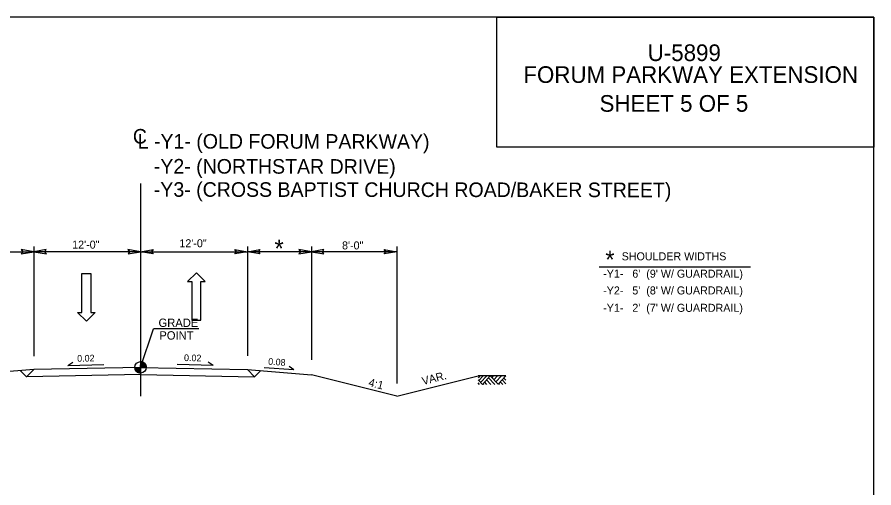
# Model space of a CAD drawing. Extents: x 1904401 to 1905163, y 193929 to 194736.
# Drawn here: x 1904562 to 1904658.3, y 194298.3 to 194351.2 of the extents above; entities that cross this region are included whole.
import ezdxf

# ---------------------------------------------------------------- set-up
doc = ezdxf.new("R2010")
doc.units = 0
for name, color, linetype in [('Old_Level_2', 7, 'Continuous'), ('Prop Dimension Text', 7, 'Continuous'), ('Prop Lane Arrow CELL', 7, 'Continuous'), ('Typical Arrow Superelevation CELL', 7, 'Continuous'), ('Typical Grade Point Symbol CELL', 7, 'Continuous'), ('Typical Hinge Slope Interstate CELL', 7, 'Continuous'), ('Typical Terminator CELL', 7, 'Continuous'), ('Typical Text Centerline CELL', 7, 'Continuous'), ('Typical Text Grade Point CELL', 7, 'Continuous')]:
    doc.layers.add(name, color=color, linetype=linetype)

msp = doc.modelspace()

# ---------------------------------------------------------------- linework, layer by layer
at = {"layer": 'Old_Level_2'}
msp.add_lwpolyline([(1904502.509, 194232.165), (1904658.329, 194232.165), (1904658.329, 194351.235), (1904502.509, 194351.235)], close=True, dxfattribs=at)
at = {"layer": 'Prop Dimension Text'}
msp.add_lwpolyline([(1904615.948, 194351.235), (1904658.329, 194351.235), (1904658.329, 194336.604), (1904615.948, 194336.604)], close=True, dxfattribs=at)
at = {"layer": 'Prop Lane Arrow CELL'}
for p, q in [((1904563.917, 194325.455), (1904563.917, 194313.121)), ((1904587.917, 194325.455), (1904587.917, 194313.144)), ((1904595.117, 194325.455), (1904595.117, 194312.685)), ((1904604.717, 194325.455), (1904604.717, 194310.019)), ((1904556.717, 194324.855), (1904563.917, 194324.855)), ((1904575.917, 194324.855), (1904563.917, 194324.855)), ((1904575.917, 194324.855), (1904587.917, 194324.855)), ((1904604.717, 194324.855), (1904587.917, 194324.855)), ((1904582.197, 194322.484), (1904581.201, 194321.503)), ((1904583.162, 194321.503), (1904582.197, 194322.484)), ((1904627.471, 194323.163), (1904644.479, 194323.163)), ((1904569.311, 194322.389), (1904570.338, 194322.389)), ((1904569.311, 194318.032), (1904569.311, 194322.389)), ((1904570.338, 194322.389), (1904570.338, 194318.032)), ((1904581.201, 194321.503), (1904581.668, 194321.503)), ((1904581.668, 194321.503), (1904581.668, 194317.146)), ((1904582.695, 194317.146), (1904582.695, 194321.503)), ((1904582.695, 194321.503), (1904583.162, 194321.503)), ((1904569.84, 194317.051), (1904568.844, 194318.032)), ((1904568.844, 194318.032), (1904569.311, 194318.032)), ((1904570.805, 194318.032), (1904569.84, 194317.051)), ((1904570.338, 194318.032), (1904570.805, 194318.032)), ((1904581.668, 194317.146), (1904582.695, 194317.146)), ((1904575.917, 194311.85), (1904563.917, 194311.61)), ((1904575.917, 194311.85), (1904587.917, 194311.61)), ((1904563.917, 194311.61), (1904556.717, 194311.01)), ((1904563.097, 194310.789), (1904562.402, 194311.483)), ((1904563.097, 194310.789), (1904563.917, 194311.61)), ((1904575.933, 194311.046), (1904563.097, 194310.789)), ((1904575.901, 194311.046), (1904588.738, 194310.789)), ((1904588.738, 194310.789), (1904587.917, 194311.61)), ((1904587.917, 194311.61), (1904595.117, 194311.01)), ((1904588.738, 194310.789), (1904589.432, 194311.483)), ((1904614.047, 194310.891), (1904613.843, 194310.672)), ((1904614.432, 194310.891), (1904613.935, 194310.358)), ((1904614.831, 194310.891), (1904614.135, 194310.144)), ((1904615.218, 194310.89), (1904614.328, 194309.935)), ((1904616.095, 194309.947), (1904615.218, 194310.89)), ((1904615.534, 194310.891), (1904615.375, 194310.72)), ((1904616.017, 194310.891), (1904615.617, 194310.46)), ((1904616.494, 194310.891), (1904615.855, 194310.204)), ((1904614.328, 194309.935), (1904613.844, 194310.457)), ((1904614.004, 194309.925), (1904613.844, 194310.097)), ((1904614.486, 194309.925), (1904614.403, 194310.014)), ((1904614.84, 194309.925), (1904614.579, 194310.205)), ((1904615.279, 194309.925), (1904614.799, 194310.44)), ((1904615.723, 194309.925), (1904615.02, 194310.679)), ((1904616.964, 194310.882), (1904616.095, 194309.947)), ((1904616.245, 194309.925), (1904616.16, 194310.016)), ((1904616.618, 194309.925), (1904616.346, 194310.217)), ((1904616.964, 194310.001), (1904616.553, 194310.44)), ((1904616.964, 194310.4), (1904616.74, 194310.64))]:
    msp.add_line(p, q, dxfattribs=at)
msp.add_lwpolyline([(1904616.964, 194310.891), (1904613.844, 194310.891)], dxfattribs=at)
at = {"layer": 'Typical Arrow Superelevation CELL'}
for p, q in [((1904567.754, 194312.076), (1904568.318, 194312.417)), ((1904567.754, 194312.076), (1904571.804, 194312.157)), ((1904584.08, 194312.076), (1904580.031, 194312.157)), ((1904584.08, 194312.076), (1904583.517, 194312.417)), ((1904593.152, 194311.567), (1904592.607, 194311.937)), ((1904593.152, 194311.567), (1904589.804, 194311.813))]:
    msp.add_line(p, q, dxfattribs=at)
at = {"layer": 'Typical Grade Point Symbol CELL'}
for p, q in [((1904575.273, 194311.862), (1904575.917, 194311.85)), ((1904575.903, 194311.205), (1904575.917, 194311.85)), ((1904575.917, 194311.85), (1904575.903, 194311.205)), ((1904575.917, 194311.85), (1904575.93, 194312.494)), ((1904576.562, 194311.837), (1904575.917, 194311.85))]:
    msp.add_line(p, q, dxfattribs=at)
for points in [[(1904575.276, 194311.862), (1904575.274, 194311.792)], [(1904575.289, 194311.862), (1904575.286, 194311.716)], [(1904575.301, 194311.862), (1904575.298, 194311.67)], [(1904575.314, 194311.861), (1904575.31, 194311.631)], [(1904575.327, 194311.861), (1904575.322, 194311.601)], [(1904575.34, 194311.861), (1904575.335, 194311.573)], [(1904575.353, 194311.861), (1904575.347, 194311.548)], [(1904575.366, 194311.86), (1904575.359, 194311.525)], [(1904575.379, 194311.86), (1904575.372, 194311.505)], [(1904575.392, 194311.86), (1904575.384, 194311.486)], [(1904575.405, 194311.86), (1904575.397, 194311.469)], [(1904575.417, 194311.859), (1904575.41, 194311.453)], [(1904575.43, 194311.859), (1904575.422, 194311.437)], [(1904575.443, 194311.859), (1904575.435, 194311.422)], [(1904575.456, 194311.859), (1904575.447, 194311.408)], [(1904575.469, 194311.858), (1904575.46, 194311.394)], [(1904575.482, 194311.858), (1904575.473, 194311.383)], [(1904575.495, 194311.858), (1904575.485, 194311.371)], [(1904575.508, 194311.858), (1904575.498, 194311.359)], [(1904575.521, 194311.857), (1904575.511, 194311.349)], [(1904575.534, 194311.857), (1904575.523, 194311.339)], [(1904575.546, 194311.857), (1904575.536, 194311.33)], [(1904575.559, 194311.857), (1904575.549, 194311.321)], [(1904575.572, 194311.856), (1904575.562, 194311.312)], [(1904575.585, 194311.856), (1904575.574, 194311.303)], [(1904575.598, 194311.856), (1904575.587, 194311.296)], [(1904575.611, 194311.856), (1904575.6, 194311.288)], [(1904575.624, 194311.855), (1904575.613, 194311.281)], [(1904575.637, 194311.855), (1904575.625, 194311.275)], [(1904575.65, 194311.855), (1904575.638, 194311.269)], [(1904575.662, 194311.855), (1904575.651, 194311.263)], [(1904575.675, 194311.854), (1904575.664, 194311.257)], [(1904575.688, 194311.854), (1904575.676, 194311.251)], [(1904575.701, 194311.854), (1904575.689, 194311.247)], [(1904575.714, 194311.854), (1904575.702, 194311.242)], [(1904575.727, 194311.853), (1904575.715, 194311.237)], [(1904575.74, 194311.853), (1904575.728, 194311.234)], [(1904575.753, 194311.853), (1904575.74, 194311.23)], [(1904575.766, 194311.853), (1904575.753, 194311.227)], [(1904575.778, 194311.852), (1904575.766, 194311.224)], [(1904575.791, 194311.852), (1904575.779, 194311.22)], [(1904575.804, 194311.852), (1904575.792, 194311.217)], [(1904575.817, 194311.852), (1904575.805, 194311.216)], [(1904575.83, 194311.851), (1904575.817, 194311.213)], [(1904575.843, 194311.851), (1904575.83, 194311.211)], [(1904575.856, 194311.851), (1904575.843, 194311.209)], [(1904575.869, 194311.851), (1904575.856, 194311.207)], [(1904575.882, 194311.85), (1904575.869, 194311.207)], [(1904575.894, 194311.85), (1904575.882, 194311.206)], [(1904575.907, 194311.85), (1904575.895, 194311.205), (1904575.895, 194311.205)], [(1904575.936, 194312.494), (1904575.936, 194312.494), (1904575.923, 194311.85)], [(1904575.949, 194312.494), (1904575.936, 194311.849)], [(1904575.961, 194312.492), (1904575.949, 194311.849)], [(1904575.974, 194312.492), (1904575.962, 194311.849)], [(1904575.987, 194312.49), (1904575.975, 194311.849)], [(1904576, 194312.488), (1904575.988, 194311.848)], [(1904576.013, 194312.487), (1904576, 194311.848)], [(1904576.026, 194312.485), (1904576.013, 194311.848)], [(1904576.039, 194312.483), (1904576.026, 194311.847)], [(1904576.051, 194312.48), (1904576.039, 194311.847)], [(1904576.064, 194312.477), (1904576.052, 194311.847)], [(1904576.077, 194312.474), (1904576.065, 194311.847)], [(1904576.09, 194312.471), (1904576.078, 194311.846)], [(1904576.103, 194312.466), (1904576.091, 194311.846)], [(1904576.116, 194312.463), (1904576.104, 194311.846)], [(1904576.128, 194312.459), (1904576.116, 194311.846)], [(1904576.141, 194312.454), (1904576.129, 194311.845)], [(1904576.154, 194312.45), (1904576.142, 194311.845)], [(1904576.167, 194312.444), (1904576.155, 194311.845)], [(1904576.18, 194312.438), (1904576.168, 194311.845)], [(1904576.192, 194312.432), (1904576.181, 194311.844)], [(1904576.205, 194312.426), (1904576.194, 194311.844)], [(1904576.218, 194312.42), (1904576.207, 194311.844)], [(1904576.231, 194312.412), (1904576.22, 194311.844)], [(1904576.243, 194312.405), (1904576.232, 194311.843)], [(1904576.256, 194312.398), (1904576.245, 194311.843)], [(1904576.269, 194312.39), (1904576.258, 194311.843)], [(1904576.282, 194312.381), (1904576.271, 194311.843)], [(1904576.294, 194312.372), (1904576.284, 194311.842)], [(1904576.307, 194312.362), (1904576.297, 194311.842)], [(1904576.32, 194312.353), (1904576.31, 194311.842)], [(1904576.333, 194312.343), (1904576.323, 194311.842)], [(1904576.345, 194312.331), (1904576.336, 194311.841)], [(1904576.358, 194312.32), (1904576.348, 194311.841)], [(1904576.37, 194312.308), (1904576.361, 194311.841)], [(1904576.383, 194312.295), (1904576.374, 194311.841)], [(1904576.396, 194312.282), (1904576.387, 194311.84)], [(1904576.408, 194312.267), (1904576.4, 194311.84)], [(1904576.421, 194312.251), (1904576.413, 194311.84)], [(1904576.434, 194312.235), (1904576.426, 194311.84)], [(1904576.446, 194312.218), (1904576.439, 194311.839)], [(1904576.459, 194312.199), (1904576.452, 194311.839)], [(1904576.471, 194312.178), (1904576.465, 194311.839)], [(1904576.484, 194312.157), (1904576.477, 194311.839)], [(1904576.496, 194312.133), (1904576.49, 194311.838)], [(1904576.508, 194312.106), (1904576.503, 194311.838)], [(1904576.521, 194312.076), (1904576.516, 194311.838)], [(1904576.533, 194312.04), (1904576.529, 194311.838)], [(1904576.545, 194311.995), (1904576.542, 194311.837)], [(1904576.557, 194311.929), (1904576.555, 194311.837)]]:
    msp.add_lwpolyline(points, dxfattribs=at)
msp.add_circle((1904575.917, 194311.85), 0.645, dxfattribs=at)
for start, end in [(178.87068, 268.87068), (358.87068, 88.87068)]:
    msp.add_arc((1904575.917, 194311.85), 0.645, start, end, dxfattribs=at)
at = {"layer": 'Typical Hinge Slope Interstate CELL'}
for q in [(1904595.117, 194311.01), (1904613.844, 194310.891)]:
    msp.add_line((1904604.717, 194308.61), q, dxfattribs=at)
at = {"layer": 'Typical Terminator CELL'}
for points in [[(1904562.511, 194324.613), (1904563.917, 194324.855), (1904562.503, 194325.105), (1904562.683, 194324.855)], [(1904565.323, 194325.098), (1904563.917, 194324.855), (1904565.331, 194324.605), (1904565.152, 194324.855)], [(1904574.511, 194324.613), (1904575.917, 194324.855), (1904574.503, 194325.105), (1904574.683, 194324.855)], [(1904577.323, 194324.613), (1904575.917, 194324.855), (1904577.331, 194325.105), (1904577.152, 194324.855)], [(1904586.511, 194325.098), (1904587.917, 194324.855), (1904586.503, 194324.605), (1904586.683, 194324.855)], [(1904589.323, 194324.613), (1904587.917, 194324.855), (1904589.331, 194325.105), (1904589.152, 194324.855)], [(1904593.711, 194324.613), (1904595.117, 194324.855), (1904593.703, 194325.105), (1904593.883, 194324.855)], [(1904596.523, 194325.098), (1904595.117, 194324.855), (1904596.531, 194324.605), (1904596.352, 194324.855)], [(1904603.311, 194325.098), (1904604.717, 194324.855), (1904603.303, 194324.605), (1904603.483, 194324.855)]]:
    msp.add_lwpolyline(points, close=True, dxfattribs=at)
at = {"layer": 'Typical Text Centerline CELL'}
msp.add_line((1904575.917, 194332.542), (1904575.917, 194308.618), dxfattribs=at)
at = {"layer": 'Typical Text Grade Point CELL'}
for p in [(1904575.917, 194311.85), (1904582.453, 194316.17)]:
    msp.add_line(p, (1904577.357, 194316.17), dxfattribs=at)

# ---------------------------------------------------------------- texts
at = {"layer": 'Prop Dimension Text'}
for s, p in [('U-5899', (1904632.91, 194346.294)), ('FORUM PARKWAY EXTENSION', (1904618.936, 194343.836)), ('SHEET 5 OF 5', (1904627.496, 194340.594))]:
    msp.add_text(s, height=1.875, dxfattribs=at).set_placement(p)
at = {"layer": 'Prop Lane Arrow CELL'}
for s, height, p in [('12\'-0"', 0.9, (1904568.23, 194325.199)), ('12\'-0"', 0.9, (1904580.28, 194325.356)), ('*', 2, (1904590.97, 194324.219)), ('8\'-0"', 0.9, (1904598.559, 194325.112)), ('*', 2, (1904628.148, 194322.969)), ('SHOULDER WIDTHS', 0.9, (1904629.985, 194323.887)), ("-Y1-   6'  (9' W/ GUARDRAIL)", 0.9, (1904627.906, 194321.933)), ("-Y2-   5'  (8' W/ GUARDRAIL)", 0.9, (1904627.906, 194320.05)), ("-Y1-   2'  (7' W/ GUARDRAIL)", 0.9, (1904627.906, 194318.095))]:
    msp.add_text(s, height=height, dxfattribs=at).set_placement(p)
for s, rotation, p in [('0.02', 1.1462, (1904568.798, 194312.48)), ('0.02', 358.8538, (1904580.795, 194312.561)), ('0.08', 355.80177, (1904590.236, 194312.152))]:
    msp.add_text(s, height=0.7499, rotation=rotation, dxfattribs=at).set_placement(p)
at = {"layer": 'Typical Hinge Slope Interstate CELL'}
for s, rotation, p in [('VAR.', 14.47161, (1904607.662, 194309.851)), ('4:1', 345.52839, (1904601.47, 194309.769))]:
    msp.add_text(s, height=0.9, rotation=rotation, dxfattribs=at).set_placement(p)
at = {"layer": 'Typical Text Centerline CELL'}
msp.add_text('C', height=1.64, dxfattribs=at).set_placement((1904575.049, 194337.015))
for s, p in [('L -Y1- (OLD FORUM PARKWAY) ', (1904575.594, 194336.455)), ('-Y2- (NORTHSTAR DRIVE) ', (1904577.408, 194333.642)), ('-Y3- (CROSS BAPTIST CHURCH ROAD/BAKER STREET) ', (1904577.408, 194331.036))]:
    msp.add_text(s, height=1.64109, rotation=359.9469, dxfattribs=at).set_placement(p)
at = {"layer": 'Typical Text Grade Point CELL'}
for s, p in [('GRADE', (1904577.935, 194316.394)), ('POINT', (1904578.026, 194314.971))]:
    msp.add_text(s, height=0.9397, rotation=360, dxfattribs=at).set_placement(p)

doc.saveas('drawing.dxf')
